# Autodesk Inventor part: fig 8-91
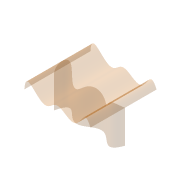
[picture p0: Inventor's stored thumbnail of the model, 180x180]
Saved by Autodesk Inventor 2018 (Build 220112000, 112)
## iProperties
Shininess: 64.0
Length Units: 11269
Angle Units: 11279
Time Units: 11290
Mass Units: 11283
Length Display Precision: 3
Angle Display Precision: 2
Compacted: True
Part Number: fig 8-91
Document SubType Name: Modeling
Created: 2003-08
Designer: Owner
Manufacturer: Standard
Standards Organization: Custom
Density: 1 g/cm^3
Material: Generic
Appearance: Default
Density: 0.0
Volumn: 0.0
Area: 0.0
PropertySet Name: Model Information
Control State: 0
Master: False
Checked Out: False
Author: Owner
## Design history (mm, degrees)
sketch "Sketch1"
  geometry: 7 further points
  constraints: 7 other
  dimensions: "d0" = 80 horizontal distance of point (40, 1.742) point (-40, -4.065); "d1" = 40 horizontal distance of point (0, 0) point (-40, -4.065)
extrude_surface "ExtrusionSrf1" sketch "Sketch1" dims "d2" = 80, "d3" = 0
sketch "Sketch2"
  geometry: L1 (40, 0)-(40, -40) reference; L2 (-40, 0)-(-40, -40) reference; 7 further points
  constraints: 2 point on line, 7 other
extrude_surface "ExtrusionSrf2" sketch "Sketch2" dims "d4" = 80, "d5" = 0
sketch "Sketch3"
  geometry: 2 further points
  constraints: 4 other
sketch "Sketch4"
  geometry: L1 (52.956, 12.425)-(-10.974, 12.425); A1 r 27.841 centre (-10.974, -15.416) between (-10.974, 12.425) and (-7.259, -43.008)
  constraints: 2 end point, 2 point on circle, 1 centre point, 1 horizontal, 1 tangent
feature "Trim1"
body "Srf1"
body "Srf2"
